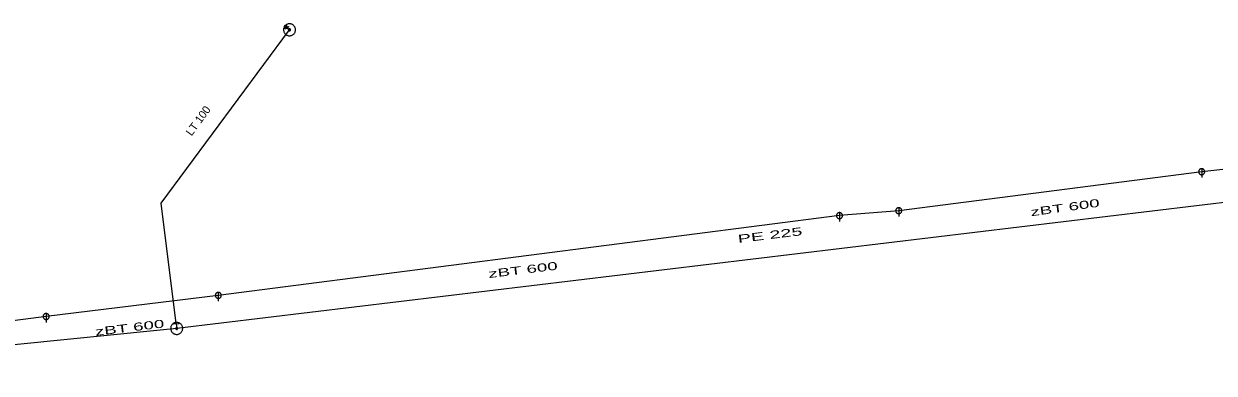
# Model space of a CAD drawing. Extents: x -687468 to -685917, y -974192 to -973456.
# Drawn here: x -686735.6 to -686636.4, y -973640.8 to -973611.7 of the extents above; entities that cross this region are included whole.
import ezdxf
from ezdxf.enums import TextEntityAlignment as Align

# ---------------------------------------------------------------- set-up
doc = ezdxf.new("R2010")
doc.units = 0
doc.header["$LTSCALE"] = 0.27
for name, color, linetype, lineweight in [('1', 7, 'Continuous', 13), ('14', 7, 'Continuous', 25), ('17', 7, 'Continuous', 25), ('22', 7, 'Continuous', 13), ('34', 7, 'Continuous', 13), ('47', 7, 'Continuous', 13), ('9', 7, 'Continuous', 13)]:
    doc.layers.add(name, color=color, linetype=linetype, lineweight=lineweight)

msp = doc.modelspace()

# ---------------------------------------------------------------- linework, layer by layer
at = {"layer": '14', "lineweight": 13}
for p, q in [((-686713.734, -973611.941), (-686713.412, -973612.179)), ((-686722.863, -973636.678), (-686722.815, -973637.075))]:
    msp.add_line(p, q, dxfattribs=at)
at = {"layer": '14'}
for p, q in [((-686617.682, -973621.851), (-686637.412, -973624.013)), ((-686637.412, -973624.013), (-686662.652, -973627.262)), ((-686667.587, -973627.675), (-686719.348, -973634.32)), ((-686662.652, -973627.262), (-686667.587, -973627.675)), ((-686719.348, -973634.32), (-686733.692, -973636.086)), ((-686733.692, -973636.086), (-686757.083, -973639.12))]:
    msp.add_line(p, q, dxfattribs=at)
at = {"layer": '17'}
for p, q in [((-686623.461, -973625.138), (-686722.815, -973637.075)), ((-686722.815, -973637.075), (-686759.568, -973640.809))]:
    msp.add_line(p, q, dxfattribs=at)
msp.add_lwpolyline([(-686722.863, -973636.678), (-686724.094, -973626.633), (-686713.412, -973612.179)], dxfattribs=at)
at = {"layer": '22'}
for p, q in [((-686637.411, -973623.761), (-686637.412, -973624.505)), ((-686667.586, -973627.423), (-686667.587, -973628.167)), ((-686662.651, -973627.01), (-686662.652, -973627.754)), ((-686719.347, -973634.068), (-686719.348, -973634.811)), ((-686733.691, -973635.834), (-686733.692, -973636.578))]:
    msp.add_line(p, q, dxfattribs=at)
for points in [[(-686637.16, -973624.013), (-686637.161, -973623.987), (-686637.165, -973623.961), (-686637.171, -973623.935), (-686637.181, -973623.911), (-686637.193, -973623.887), (-686637.207, -973623.865), (-686637.224, -973623.844), (-686637.242, -973623.826), (-686637.263, -973623.809), (-686637.285, -973623.795), (-686637.309, -973623.783), (-686637.333, -973623.773), (-686637.359, -973623.767), (-686637.385, -973623.763), (-686637.411, -973623.761), (-686637.437, -973623.762), (-686637.463, -973623.766), (-686637.489, -973623.772), (-686637.514, -973623.782), (-686637.537, -973623.794), (-686637.559, -973623.808), (-686637.58, -973623.825), (-686637.598, -973623.843), (-686637.615, -973623.864), (-686637.629, -973623.886), (-686637.641, -973623.91), (-686637.651, -973623.934), (-686637.658, -973623.96), (-686637.662, -973623.986), (-686637.664, -973624.012), (-686637.663, -973624.038), (-686637.659, -973624.064), (-686637.652, -973624.09), (-686637.642, -973624.115), (-686637.63, -973624.138), (-686637.616, -973624.16), (-686637.599, -973624.181), (-686637.581, -973624.199), (-686637.56, -973624.216), (-686637.538, -973624.23), (-686637.515, -973624.242), (-686637.49, -973624.252), (-686637.464, -973624.259), (-686637.438, -973624.263), (-686637.412, -973624.265), (-686637.386, -973624.264), (-686637.36, -973624.26), (-686637.334, -973624.253), (-686637.31, -973624.243), (-686637.286, -973624.231), (-686637.264, -973624.217), (-686637.243, -973624.2), (-686637.225, -973624.182), (-686637.208, -973624.161), (-686637.194, -973624.139), (-686637.182, -973624.116), (-686637.172, -973624.091), (-686637.166, -973624.065), (-686637.162, -973624.039)], [(-686667.335, -973627.675), (-686667.336, -973627.649), (-686667.34, -973627.623), (-686667.346, -973627.597), (-686667.356, -973627.573), (-686667.368, -973627.549), (-686667.382, -973627.527), (-686667.399, -973627.506), (-686667.417, -973627.488), (-686667.438, -973627.471), (-686667.46, -973627.457), (-686667.484, -973627.445), (-686667.508, -973627.435), (-686667.534, -973627.429), (-686667.56, -973627.425), (-686667.586, -973627.423), (-686667.612, -973627.424), (-686667.638, -973627.428), (-686667.664, -973627.434), (-686667.689, -973627.444), (-686667.712, -973627.456), (-686667.734, -973627.47), (-686667.755, -973627.487), (-686667.773, -973627.505), (-686667.79, -973627.526), (-686667.804, -973627.548), (-686667.816, -973627.572), (-686667.826, -973627.596), (-686667.833, -973627.622), (-686667.837, -973627.648), (-686667.839, -973627.674), (-686667.838, -973627.7), (-686667.834, -973627.726), (-686667.827, -973627.752), (-686667.817, -973627.777), (-686667.805, -973627.8), (-686667.791, -973627.822), (-686667.774, -973627.843), (-686667.756, -973627.861), (-686667.735, -973627.878), (-686667.713, -973627.892), (-686667.69, -973627.904), (-686667.665, -973627.914), (-686667.639, -973627.921), (-686667.613, -973627.925), (-686667.587, -973627.927), (-686667.561, -973627.926), (-686667.535, -973627.922), (-686667.509, -973627.915), (-686667.485, -973627.905), (-686667.461, -973627.893), (-686667.439, -973627.879), (-686667.418, -973627.862), (-686667.4, -973627.844), (-686667.383, -973627.823), (-686667.369, -973627.801), (-686667.357, -973627.778), (-686667.347, -973627.753), (-686667.341, -973627.727), (-686667.337, -973627.701)], [(-686662.4, -973627.262), (-686662.401, -973627.236), (-686662.405, -973627.21), (-686662.411, -973627.184), (-686662.421, -973627.16), (-686662.433, -973627.136), (-686662.447, -973627.114), (-686662.464, -973627.093), (-686662.482, -973627.075), (-686662.503, -973627.058), (-686662.525, -973627.044), (-686662.549, -973627.032), (-686662.573, -973627.022), (-686662.599, -973627.016), (-686662.625, -973627.012), (-686662.651, -973627.01), (-686662.677, -973627.011), (-686662.703, -973627.015), (-686662.729, -973627.021), (-686662.754, -973627.031), (-686662.777, -973627.043), (-686662.799, -973627.057), (-686662.82, -973627.074), (-686662.838, -973627.092), (-686662.855, -973627.113), (-686662.869, -973627.135), (-686662.881, -973627.159), (-686662.891, -973627.183), (-686662.898, -973627.209), (-686662.902, -973627.235), (-686662.904, -973627.261), (-686662.903, -973627.287), (-686662.899, -973627.313), (-686662.892, -973627.339), (-686662.882, -973627.364), (-686662.87, -973627.387), (-686662.856, -973627.409), (-686662.839, -973627.43), (-686662.821, -973627.448), (-686662.8, -973627.465), (-686662.778, -973627.479), (-686662.755, -973627.491), (-686662.73, -973627.501), (-686662.704, -973627.508), (-686662.678, -973627.512), (-686662.652, -973627.514), (-686662.626, -973627.513), (-686662.6, -973627.509), (-686662.574, -973627.502), (-686662.55, -973627.492), (-686662.526, -973627.48), (-686662.504, -973627.466), (-686662.483, -973627.449), (-686662.465, -973627.431), (-686662.448, -973627.41), (-686662.434, -973627.388), (-686662.422, -973627.365), (-686662.412, -973627.34), (-686662.406, -973627.314), (-686662.402, -973627.288)], [(-686719.096, -973634.32), (-686719.097, -973634.294), (-686719.101, -973634.268), (-686719.107, -973634.242), (-686719.117, -973634.218), (-686719.129, -973634.194), (-686719.143, -973634.172), (-686719.16, -973634.151), (-686719.178, -973634.133), (-686719.199, -973634.116), (-686719.221, -973634.102), (-686719.245, -973634.09), (-686719.269, -973634.08), (-686719.295, -973634.074), (-686719.321, -973634.07), (-686719.347, -973634.068), (-686719.373, -973634.069), (-686719.399, -973634.073), (-686719.425, -973634.079), (-686719.45, -973634.089), (-686719.473, -973634.101), (-686719.495, -973634.115), (-686719.516, -973634.132), (-686719.534, -973634.15), (-686719.551, -973634.171), (-686719.565, -973634.193), (-686719.577, -973634.217), (-686719.587, -973634.241), (-686719.594, -973634.267), (-686719.598, -973634.293), (-686719.6, -973634.319), (-686719.599, -973634.345), (-686719.595, -973634.371), (-686719.588, -973634.397), (-686719.578, -973634.422), (-686719.566, -973634.445), (-686719.552, -973634.467), (-686719.535, -973634.488), (-686719.517, -973634.506), (-686719.496, -973634.523), (-686719.474, -973634.537), (-686719.451, -973634.549), (-686719.426, -973634.559), (-686719.4, -973634.566), (-686719.374, -973634.57), (-686719.348, -973634.571), (-686719.322, -973634.571), (-686719.296, -973634.567), (-686719.27, -973634.56), (-686719.246, -973634.55), (-686719.222, -973634.538), (-686719.2, -973634.524), (-686719.179, -973634.507), (-686719.161, -973634.489), (-686719.144, -973634.468), (-686719.13, -973634.446), (-686719.118, -973634.423), (-686719.108, -973634.398), (-686719.102, -973634.372), (-686719.098, -973634.346)], [(-686733.44, -973636.086), (-686733.441, -973636.06), (-686733.445, -973636.034), (-686733.451, -973636.008), (-686733.461, -973635.984), (-686733.473, -973635.96), (-686733.487, -973635.938), (-686733.504, -973635.917), (-686733.522, -973635.899), (-686733.543, -973635.882), (-686733.565, -973635.868), (-686733.589, -973635.856), (-686733.613, -973635.846), (-686733.639, -973635.84), (-686733.665, -973635.836), (-686733.691, -973635.834), (-686733.717, -973635.835), (-686733.743, -973635.839), (-686733.769, -973635.845), (-686733.794, -973635.855), (-686733.817, -973635.867), (-686733.839, -973635.881), (-686733.86, -973635.898), (-686733.878, -973635.916), (-686733.895, -973635.937), (-686733.909, -973635.959), (-686733.921, -973635.983), (-686733.931, -973636.007), (-686733.938, -973636.033), (-686733.942, -973636.059), (-686733.944, -973636.085), (-686733.943, -973636.111), (-686733.939, -973636.137), (-686733.932, -973636.163), (-686733.922, -973636.188), (-686733.91, -973636.211), (-686733.896, -973636.233), (-686733.879, -973636.254), (-686733.861, -973636.272), (-686733.84, -973636.289), (-686733.818, -973636.303), (-686733.795, -973636.315), (-686733.77, -973636.325), (-686733.744, -973636.332), (-686733.718, -973636.336), (-686733.692, -973636.338), (-686733.666, -973636.337), (-686733.64, -973636.333), (-686733.614, -973636.326), (-686733.59, -973636.316), (-686733.566, -973636.304), (-686733.544, -973636.29), (-686733.523, -973636.273), (-686733.505, -973636.255), (-686733.488, -973636.234), (-686733.474, -973636.212), (-686733.462, -973636.189), (-686733.452, -973636.164), (-686733.446, -973636.138), (-686733.442, -973636.112)]]:
    msp.add_lwpolyline(points, close=True, dxfattribs=at)
at = {"layer": '34'}
msp.add_line((-686723.11, -973636.699), (-686722.615, -973636.656), dxfattribs=at)
at = {"layer": '47'}
for points in [[(-686712.915, -973612.117), (-686712.925, -973612.066), (-686712.939, -973612.015), (-686712.959, -973611.967), (-686712.983, -973611.921), (-686713.013, -973611.877), (-686713.047, -973611.837), (-686713.085, -973611.801), (-686713.126, -973611.769), (-686713.17, -973611.741), (-686713.217, -973611.718), (-686713.266, -973611.7), (-686713.317, -973611.688), (-686713.369, -973611.68), (-686713.421, -973611.679), (-686713.473, -973611.682), (-686713.524, -973611.692), (-686713.575, -973611.706), (-686713.624, -973611.726), (-686713.669, -973611.75), (-686713.713, -973611.78), (-686713.753, -973611.814), (-686713.79, -973611.852), (-686713.822, -973611.893), (-686713.85, -973611.937), (-686713.872, -973611.984), (-686713.89, -973612.033), (-686713.903, -973612.084), (-686713.91, -973612.136), (-686713.911, -973612.188), (-686713.908, -973612.24), (-686713.898, -973612.291), (-686713.884, -973612.342), (-686713.865, -973612.391), (-686713.84, -973612.436), (-686713.81, -973612.48), (-686713.777, -973612.52), (-686713.739, -973612.557), (-686713.698, -973612.589), (-686713.653, -973612.617), (-686713.606, -973612.639), (-686713.557, -973612.657), (-686713.507, -973612.67), (-686713.454, -973612.677), (-686713.402, -973612.678), (-686713.35, -973612.675), (-686713.299, -973612.665), (-686713.248, -973612.651), (-686713.2, -973612.632), (-686713.154, -973612.607), (-686713.11, -973612.577), (-686713.07, -973612.544), (-686713.034, -973612.506), (-686713.002, -973612.465), (-686712.974, -973612.42), (-686712.951, -973612.373), (-686712.933, -973612.324), (-686712.921, -973612.274), (-686712.913, -973612.221), (-686712.912, -973612.169)], [(-686713.33, -973612.168), (-686713.331, -973612.159), (-686713.334, -973612.152), (-686713.337, -973612.144), (-686713.341, -973612.137), (-686713.346, -973612.129), (-686713.352, -973612.123), (-686713.358, -973612.116), (-686713.364, -973612.111), (-686713.372, -973612.107), (-686713.38, -973612.103), (-686713.388, -973612.1), (-686713.396, -973612.098), (-686713.404, -973612.097), (-686713.413, -973612.096), (-686713.422, -973612.097), (-686713.431, -973612.098), (-686713.438, -973612.101), (-686713.446, -973612.104), (-686713.453, -973612.108), (-686713.461, -973612.113), (-686713.467, -973612.119), (-686713.474, -973612.125), (-686713.479, -973612.131), (-686713.484, -973612.139), (-686713.487, -973612.147), (-686713.49, -973612.155), (-686713.492, -973612.163), (-686713.493, -973612.171), (-686713.494, -973612.18), (-686713.493, -973612.189), (-686713.492, -973612.198), (-686713.489, -973612.205), (-686713.486, -973612.213), (-686713.482, -973612.22), (-686713.477, -973612.228), (-686713.472, -973612.234), (-686713.465, -973612.241), (-686713.459, -973612.246), (-686713.451, -973612.251), (-686713.443, -973612.254), (-686713.435, -973612.257), (-686713.427, -973612.259), (-686713.419, -973612.26), (-686713.41, -973612.261), (-686713.401, -973612.26), (-686713.392, -973612.259), (-686713.385, -973612.256), (-686713.377, -973612.253), (-686713.37, -973612.249), (-686713.362, -973612.244), (-686713.356, -973612.239), (-686713.349, -973612.232), (-686713.344, -973612.226), (-686713.34, -973612.218), (-686713.336, -973612.21), (-686713.333, -973612.202), (-686713.331, -973612.194), (-686713.33, -973612.186), (-686713.329, -973612.177)], [(-686722.318, -973637.013), (-686722.328, -973636.962), (-686722.342, -973636.911), (-686722.362, -973636.863), (-686722.386, -973636.817), (-686722.416, -973636.773), (-686722.45, -973636.733), (-686722.488, -973636.697), (-686722.529, -973636.665), (-686722.573, -973636.637), (-686722.62, -973636.614), (-686722.669, -973636.596), (-686722.72, -973636.584), (-686722.772, -973636.576), (-686722.824, -973636.575), (-686722.876, -973636.578), (-686722.927, -973636.588), (-686722.978, -973636.602), (-686723.027, -973636.622), (-686723.072, -973636.646), (-686723.116, -973636.676), (-686723.156, -973636.71), (-686723.193, -973636.748), (-686723.225, -973636.789), (-686723.253, -973636.833), (-686723.275, -973636.88), (-686723.293, -973636.929), (-686723.306, -973636.98), (-686723.313, -973637.032), (-686723.314, -973637.084), (-686723.311, -973637.136), (-686723.301, -973637.187), (-686723.287, -973637.238), (-686723.268, -973637.287), (-686723.243, -973637.332), (-686723.213, -973637.376), (-686723.18, -973637.416), (-686723.142, -973637.453), (-686723.101, -973637.485), (-686723.056, -973637.513), (-686723.009, -973637.535), (-686722.96, -973637.553), (-686722.91, -973637.566), (-686722.857, -973637.573), (-686722.805, -973637.574), (-686722.753, -973637.571), (-686722.702, -973637.561), (-686722.651, -973637.547), (-686722.603, -973637.528), (-686722.557, -973637.503), (-686722.513, -973637.473), (-686722.473, -973637.44), (-686722.437, -973637.402), (-686722.405, -973637.361), (-686722.377, -973637.316), (-686722.354, -973637.269), (-686722.336, -973637.22), (-686722.324, -973637.17), (-686722.316, -973637.117), (-686722.315, -973637.065)], [(-686722.733, -973637.064), (-686722.734, -973637.055), (-686722.737, -973637.048), (-686722.74, -973637.04), (-686722.744, -973637.033), (-686722.749, -973637.025), (-686722.755, -973637.019), (-686722.761, -973637.012), (-686722.767, -973637.007), (-686722.775, -973637.003), (-686722.783, -973636.999), (-686722.791, -973636.996), (-686722.799, -973636.994), (-686722.807, -973636.993), (-686722.816, -973636.992), (-686722.825, -973636.993), (-686722.834, -973636.994), (-686722.841, -973636.997), (-686722.849, -973637), (-686722.856, -973637.004), (-686722.864, -973637.009), (-686722.87, -973637.015), (-686722.877, -973637.021), (-686722.882, -973637.027), (-686722.887, -973637.035), (-686722.89, -973637.043), (-686722.893, -973637.051), (-686722.895, -973637.059), (-686722.896, -973637.067), (-686722.897, -973637.076), (-686722.896, -973637.085), (-686722.895, -973637.094), (-686722.892, -973637.101), (-686722.889, -973637.109), (-686722.885, -973637.116), (-686722.88, -973637.124), (-686722.875, -973637.13), (-686722.868, -973637.137), (-686722.862, -973637.142), (-686722.854, -973637.147), (-686722.846, -973637.15), (-686722.838, -973637.153), (-686722.83, -973637.155), (-686722.822, -973637.156), (-686722.813, -973637.157), (-686722.804, -973637.156), (-686722.795, -973637.155), (-686722.788, -973637.152), (-686722.78, -973637.149), (-686722.773, -973637.145), (-686722.765, -973637.14), (-686722.759, -973637.135), (-686722.752, -973637.128), (-686722.747, -973637.122), (-686722.743, -973637.114), (-686722.739, -973637.106), (-686722.736, -973637.098), (-686722.734, -973637.09), (-686722.733, -973637.082), (-686722.732, -973637.073)]]:
    msp.add_lwpolyline(points, close=True, dxfattribs=at)
at = {"layer": '9'}
msp.add_line((-686713.608, -973611.941), (-686713.482, -973611.941), dxfattribs=at)
for points in [[(-686713.734, -973612.067), (-686713.721, -973612.066), (-686713.708, -973612.064), (-686713.695, -973612.061), (-686713.683, -973612.056), (-686713.671, -973612.05), (-686713.66, -973612.043), (-686713.65, -973612.035), (-686713.64, -973612.025), (-686713.632, -973612.015), (-686713.625, -973612.004), (-686713.619, -973611.992), (-686713.614, -973611.98), (-686713.611, -973611.967), (-686713.609, -973611.954), (-686713.608, -973611.941), (-686713.608, -973611.928), (-686713.61, -973611.915), (-686713.613, -973611.902), (-686713.618, -973611.89), (-686713.624, -973611.878), (-686713.631, -973611.867), (-686713.639, -973611.857), (-686713.649, -973611.847), (-686713.659, -973611.839), (-686713.67, -973611.832), (-686713.682, -973611.826), (-686713.694, -973611.821), (-686713.707, -973611.818), (-686713.72, -973611.816), (-686713.733, -973611.815), (-686713.746, -973611.815), (-686713.759, -973611.817), (-686713.772, -973611.82), (-686713.784, -973611.825), (-686713.796, -973611.831), (-686713.807, -973611.838), (-686713.817, -973611.846), (-686713.827, -973611.856), (-686713.835, -973611.866), (-686713.842, -973611.877), (-686713.848, -973611.889), (-686713.853, -973611.901), (-686713.856, -973611.914), (-686713.858, -973611.927), (-686713.86, -973611.94), (-686713.859, -973611.953), (-686713.857, -973611.966), (-686713.854, -973611.979), (-686713.849, -973611.991), (-686713.843, -973612.003), (-686713.836, -973612.014), (-686713.828, -973612.024), (-686713.818, -973612.034), (-686713.808, -973612.042), (-686713.797, -973612.049), (-686713.785, -973612.055), (-686713.773, -973612.06), (-686713.76, -973612.063), (-686713.747, -973612.065)], [(-686713.734, -973612.047), (-686713.723, -973612.047), (-686713.712, -973612.045), (-686713.701, -973612.042), (-686713.691, -973612.038), (-686713.681, -973612.033), (-686713.672, -973612.027), (-686713.663, -973612.02), (-686713.655, -973612.012), (-686713.648, -973612.003), (-686713.642, -973611.994), (-686713.637, -973611.984), (-686713.633, -973611.974), (-686713.63, -973611.963), (-686713.628, -973611.952), (-686713.628, -973611.941), (-686713.627, -973611.93), (-686713.629, -973611.919), (-686713.632, -973611.908), (-686713.636, -973611.898), (-686713.641, -973611.888), (-686713.647, -973611.879), (-686713.654, -973611.87), (-686713.662, -973611.862), (-686713.671, -973611.855), (-686713.68, -973611.849), (-686713.69, -973611.844), (-686713.7, -973611.84), (-686713.711, -973611.837), (-686713.722, -973611.835), (-686713.733, -973611.835), (-686713.744, -973611.834), (-686713.755, -973611.836), (-686713.766, -973611.839), (-686713.776, -973611.843), (-686713.786, -973611.848), (-686713.795, -973611.854), (-686713.804, -973611.861), (-686713.812, -973611.869), (-686713.819, -973611.878), (-686713.825, -973611.887), (-686713.83, -973611.897), (-686713.834, -973611.907), (-686713.837, -973611.918), (-686713.839, -973611.929), (-686713.84, -973611.94), (-686713.84, -973611.951), (-686713.838, -973611.962), (-686713.835, -973611.973), (-686713.831, -973611.983), (-686713.826, -973611.993), (-686713.82, -973612.002), (-686713.813, -973612.011), (-686713.805, -973612.019), (-686713.796, -973612.026), (-686713.787, -973612.032), (-686713.777, -973612.037), (-686713.767, -973612.041), (-686713.756, -973612.044), (-686713.745, -973612.046)], [(-686713.734, -973612.028), (-686713.725, -973612.027), (-686713.716, -973612.026), (-686713.707, -973612.023), (-686713.699, -973612.02), (-686713.691, -973612.016), (-686713.683, -973612.011), (-686713.676, -973612.005), (-686713.67, -973611.999), (-686713.664, -973611.992), (-686713.659, -973611.984), (-686713.655, -973611.976), (-686713.652, -973611.968), (-686713.649, -973611.959), (-686713.648, -973611.95), (-686713.647, -973611.941), (-686713.647, -973611.932), (-686713.648, -973611.923), (-686713.651, -973611.914), (-686713.654, -973611.906), (-686713.658, -973611.898), (-686713.663, -973611.89), (-686713.669, -973611.883), (-686713.675, -973611.877), (-686713.682, -973611.871), (-686713.69, -973611.866), (-686713.698, -973611.862), (-686713.706, -973611.859), (-686713.715, -973611.856), (-686713.724, -973611.855), (-686713.733, -973611.853), (-686713.742, -973611.854), (-686713.751, -973611.855), (-686713.76, -973611.858), (-686713.768, -973611.861), (-686713.776, -973611.865), (-686713.784, -973611.87), (-686713.791, -973611.876), (-686713.797, -973611.882), (-686713.803, -973611.889), (-686713.808, -973611.897), (-686713.812, -973611.905), (-686713.815, -973611.913), (-686713.818, -973611.922), (-686713.819, -973611.931), (-686713.821, -973611.94), (-686713.82, -973611.949), (-686713.819, -973611.958), (-686713.816, -973611.967), (-686713.813, -973611.975), (-686713.809, -973611.983), (-686713.804, -973611.991), (-686713.798, -973611.998), (-686713.792, -973612.004), (-686713.785, -973612.01), (-686713.777, -973612.015), (-686713.769, -973612.019), (-686713.761, -973612.022), (-686713.752, -973612.025), (-686713.743, -973612.026)], [(-686713.734, -973612.008), (-686713.727, -973612.008), (-686713.72, -973612.006), (-686713.713, -973612.005), (-686713.707, -973612.002), (-686713.701, -973611.999), (-686713.695, -973611.995), (-686713.689, -973611.991), (-686713.684, -973611.986), (-686713.68, -973611.98), (-686713.676, -973611.974), (-686713.673, -973611.968), (-686713.67, -973611.962), (-686713.669, -973611.955), (-686713.667, -973611.948), (-686713.667, -973611.941), (-686713.666, -973611.934), (-686713.668, -973611.927), (-686713.669, -973611.92), (-686713.672, -973611.914), (-686713.675, -973611.907), (-686713.679, -973611.902), (-686713.683, -973611.896), (-686713.688, -973611.891), (-686713.694, -973611.887), (-686713.7, -973611.883), (-686713.706, -973611.88), (-686713.712, -973611.877), (-686713.719, -973611.875), (-686713.726, -973611.874), (-686713.733, -973611.874), (-686713.74, -973611.873), (-686713.747, -973611.874), (-686713.754, -973611.876), (-686713.76, -973611.879), (-686713.767, -973611.882), (-686713.772, -973611.886), (-686713.778, -973611.89), (-686713.783, -973611.895), (-686713.787, -973611.901), (-686713.791, -973611.906), (-686713.794, -973611.913), (-686713.797, -973611.919), (-686713.799, -973611.926), (-686713.8, -973611.933), (-686713.801, -973611.94), (-686713.801, -973611.947), (-686713.8, -973611.954), (-686713.798, -973611.961), (-686713.795, -973611.967), (-686713.792, -973611.973), (-686713.788, -973611.979), (-686713.784, -973611.985), (-686713.779, -973611.99), (-686713.773, -973611.994), (-686713.768, -973611.998), (-686713.761, -973612.001), (-686713.755, -973612.004), (-686713.748, -973612.005), (-686713.741, -973612.007)], [(-686713.734, -973611.988), (-686713.729, -973611.988), (-686713.724, -973611.987), (-686713.719, -973611.986), (-686713.715, -973611.984), (-686713.71, -973611.982), (-686713.706, -973611.979), (-686713.703, -973611.976), (-686713.699, -973611.972), (-686713.696, -973611.969), (-686713.693, -973611.965), (-686713.691, -973611.96), (-686713.689, -973611.956), (-686713.688, -973611.951), (-686713.687, -973611.946), (-686713.687, -973611.941), (-686713.686, -973611.936), (-686713.687, -973611.931), (-686713.688, -973611.926), (-686713.69, -973611.922), (-686713.692, -973611.917), (-686713.695, -973611.913), (-686713.698, -973611.909), (-686713.702, -973611.906), (-686713.705, -973611.903), (-686713.709, -973611.9), (-686713.714, -973611.898), (-686713.718, -973611.896), (-686713.723, -973611.895), (-686713.728, -973611.894), (-686713.733, -973611.894), (-686713.738, -973611.893), (-686713.743, -973611.894), (-686713.748, -973611.895), (-686713.752, -973611.897), (-686713.757, -973611.899), (-686713.761, -973611.902), (-686713.765, -973611.905), (-686713.768, -973611.908), (-686713.771, -973611.912), (-686713.774, -973611.916), (-686713.776, -973611.921), (-686713.778, -973611.925), (-686713.779, -973611.93), (-686713.78, -973611.935), (-686713.781, -973611.94), (-686713.781, -973611.945), (-686713.78, -973611.95), (-686713.779, -973611.955), (-686713.777, -973611.959), (-686713.775, -973611.964), (-686713.772, -973611.968), (-686713.769, -973611.971), (-686713.766, -973611.975), (-686713.762, -973611.978), (-686713.758, -973611.981), (-686713.753, -973611.983), (-686713.749, -973611.985), (-686713.744, -973611.986), (-686713.739, -973611.987)], [(-686713.734, -973611.968), (-686713.731, -973611.968), (-686713.728, -973611.968), (-686713.726, -973611.967), (-686713.723, -973611.966), (-686713.72, -973611.965), (-686713.718, -973611.963), (-686713.716, -973611.961), (-686713.714, -973611.959), (-686713.712, -973611.957), (-686713.71, -973611.955), (-686713.709, -973611.952), (-686713.708, -973611.949), (-686713.707, -973611.947), (-686713.707, -973611.944), (-686713.707, -973611.941), (-686713.706, -973611.938), (-686713.706, -973611.935), (-686713.707, -973611.932), (-686713.708, -973611.93), (-686713.709, -973611.927), (-686713.711, -973611.925), (-686713.713, -973611.922), (-686713.715, -973611.92), (-686713.717, -973611.919), (-686713.719, -973611.917), (-686713.722, -973611.916), (-686713.725, -973611.915), (-686713.727, -973611.914), (-686713.73, -973611.914), (-686713.733, -973611.913), (-686713.736, -973611.913), (-686713.739, -973611.913), (-686713.742, -973611.914), (-686713.744, -973611.915), (-686713.747, -973611.916), (-686713.749, -973611.918), (-686713.752, -973611.919), (-686713.754, -973611.921), (-686713.755, -973611.924), (-686713.757, -973611.926), (-686713.758, -973611.929), (-686713.759, -973611.931), (-686713.76, -973611.934), (-686713.761, -973611.937), (-686713.762, -973611.94), (-686713.761, -973611.943), (-686713.761, -973611.946), (-686713.76, -973611.948), (-686713.759, -973611.951), (-686713.758, -973611.954), (-686713.756, -973611.956), (-686713.755, -973611.958), (-686713.753, -973611.96), (-686713.75, -973611.962), (-686713.748, -973611.964), (-686713.745, -973611.965), (-686713.743, -973611.966), (-686713.74, -973611.967), (-686713.737, -973611.967)], [(-686713.734, -973611.949), (-686713.733, -973611.949), (-686713.732, -973611.949), (-686713.732, -973611.948), (-686713.731, -973611.948), (-686713.73, -973611.948), (-686713.729, -973611.947), (-686713.729, -973611.947), (-686713.728, -973611.946), (-686713.728, -973611.946), (-686713.727, -973611.945), (-686713.727, -973611.944), (-686713.727, -973611.943), (-686713.726, -973611.943), (-686713.726, -973611.942), (-686713.726, -973611.941), (-686713.726, -973611.94), (-686713.726, -973611.939), (-686713.727, -973611.939), (-686713.727, -973611.938), (-686713.726, -973611.937), (-686713.727, -973611.936), (-686713.727, -973611.936), (-686713.728, -973611.935), (-686713.728, -973611.935), (-686713.729, -973611.934), (-686713.73, -973611.934), (-686713.731, -973611.933), (-686713.731, -973611.933), (-686713.732, -973611.933), (-686713.733, -973611.933), (-686713.734, -973611.933), (-686713.735, -973611.933), (-686713.735, -973611.933), (-686713.736, -973611.933), (-686713.737, -973611.933), (-686713.738, -973611.934), (-686713.738, -973611.934), (-686713.739, -973611.935), (-686713.739, -973611.935), (-686713.74, -973611.936), (-686713.74, -973611.937), (-686713.742, -973611.938), (-686713.742, -973611.938), (-686713.742, -973611.939), (-686713.742, -973611.94), (-686713.742, -973611.941), (-686713.742, -973611.942), (-686713.742, -973611.942), (-686713.741, -973611.943), (-686713.741, -973611.944), (-686713.74, -973611.945), (-686713.74, -973611.945), (-686713.739, -973611.946), (-686713.739, -973611.946), (-686713.738, -973611.947), (-686713.737, -973611.947), (-686713.736, -973611.947), (-686713.736, -973611.948), (-686713.735, -973611.948)]]:
    msp.add_lwpolyline(points, close=True, dxfattribs=at)
msp.add_lwpolyline([(-686713.516, -973611.91), (-686713.482, -973611.941), (-686713.517, -973611.972)], dxfattribs=at)

# ---------------------------------------------------------------- texts
at = {"layer": '1'}
msp.add_text('LT 100', height=0.6667, rotation=54, dxfattribs=at).set_placement((-686720.758, -973619.957), align=Align.CENTER)
for s, rotation, width, p in [('zBT 600 ', 8, 1.75, (-686648.54, -973627.291)), ('PE 225', 7, 1.85, (-686673.336, -973629.622)), ('zBT 600 ', 7, 1.75, (-686693.709, -973632.495)), ('zBT 600 ', 7, 1.75, (-686726.484, -973637.315))]:
    msp.add_text(s, height=0.6667, rotation=rotation, dxfattribs=dict(at, width=width)).set_placement(p, align=Align.CENTER)

doc.saveas('drawing.dxf')
